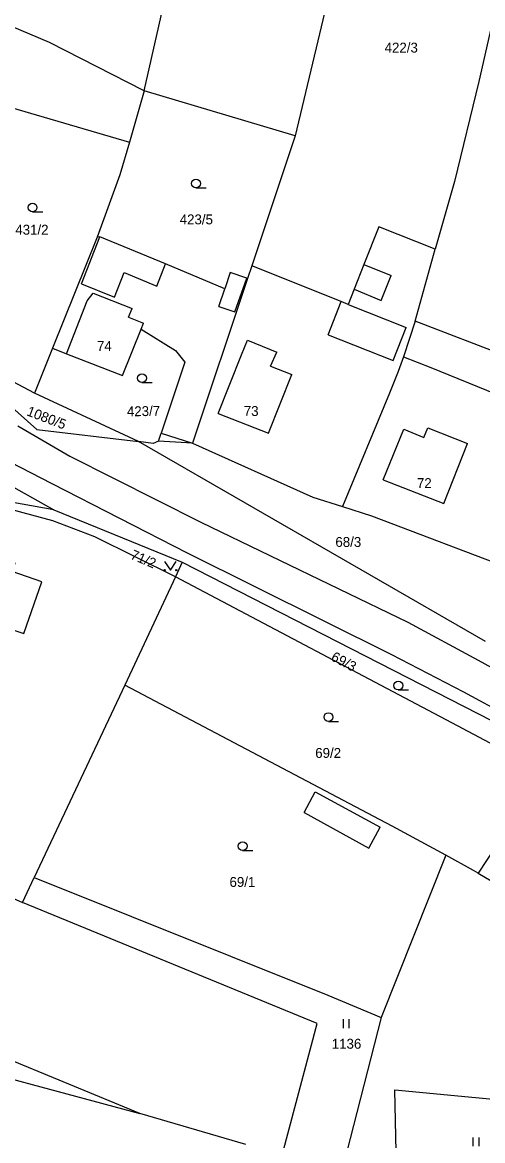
# Model space of a CAD drawing. Extents: x -746176 to -739709, y -1128407 to -1124482.
# Drawn here: x -742472.1 to -742393.3, y -1126052.3 to -1125860.6 of the extents above; entities that cross this region are included whole.
import ezdxf

# ---------------------------------------------------------------- set-up
doc = ezdxf.new("R2010")
doc.units = 0
for name, color, linetype in [('Hranice parcel', 7, 'Continuous'), ('Parcelní čísla', 7, 'Continuous'), ('Vnitřní kresba', 7, 'Continuous'), ('Značky kultur', 7, 'Continuous')]:
    doc.layers.add(name, color=color, linetype=linetype)

msp = doc.modelspace()

# ---------------------------------------------------------------- linework, layer by layer
at = {"layer": 'Hranice parcel'}
for p, q in [((-742411.59, -1125821.74), (-742425.41, -1125880.06)), ((-742491.48, -1125870.12), (-742453.8, -1125881.12)), ((-742451.26, -1125872.3), (-742453.8, -1125881.12)), ((-742425.41, -1125880.06), (-742451.26, -1125872.3)), ((-742425.41, -1125880.06), (-742432.86, -1125902.34)), ((-742459.32, -1125897.41), (-742466.99, -1125916.45)), ((-742404.91, -1125911.78), (-742401.44, -1125899.49)), ((-742432.86, -1125902.34), (-742433.58, -1125904.47)), ((-742433.58, -1125904.47), (-742443.02, -1125932.7)), ((-742470.08, -1125924.13), (-742486.25, -1125915.58)), ((-742466.99, -1125916.45), (-742470.08, -1125924.13)), ((-742452.23, -1125932.44), (-742470.08, -1125924.13)), ((-742392.86, -1125966.72), (-742452.23, -1125932.44)), ((-742485.76, -1125933.54), (-742466.73, -1125944.13)), ((-742466.73, -1125944.13), (-742444.75, -1125953.11)), ((-742444.75, -1125953.11), (-742445.94, -1125955.65)), ((-742445.94, -1125955.65), (-742454.6, -1125974.2)), ((-742454.6, -1125974.2), (-742470.09, -1126007.17)), ((-742399.65, -1126003.37), (-742410.68, -1126031.18)), ((-742472.11, -1126011.47), (-742470.09, -1126007.17)), ((-742452.02, -1126047.65), (-742529.61, -1126015.62)), ((-742410.68, -1126031.18), (-742417.35, -1126057.17)), ((-742433.87, -1126052.94), (-742452.02, -1126047.65))]:
    msp.add_line(p, q, dxfattribs=at)
for points in [[(-742451.26, -1125872.3), (-742423.93, -1125751.58), (-742396.6, -1125630.87)], [(-742451.26, -1125872.3), (-742467.46, -1125864.05), (-742487.36, -1125855.55)], [(-742391.8, -1125861.15), (-742394.01, -1125870.7), (-742398.15, -1125887.84), (-742401.44, -1125899.49)], [(-742453.8, -1125881.12), (-742455.42, -1125886.74), (-742459.32, -1125897.41)], [(-742401.44, -1125899.49), (-742411.12, -1125895.65), (-742413.66, -1125902.11), (-742415.31, -1125906.31), (-742416.34, -1125908.93), (-742417.54, -1125908.45), (-742432.86, -1125902.34)], [(-742433.58, -1125904.47), (-742433.71, -1125904.43), (-742436.54, -1125903.47), (-742437.49, -1125906.29), (-742447.62, -1125901.95), (-742458.86, -1125897.36), (-742459.32, -1125897.41)], [(-742466.99, -1125916.45), (-742464.6, -1125917.38), (-742455, -1125921.11), (-742451.78, -1125913.15), (-742445.93, -1125916.84), (-742444.31, -1125918.83), (-742448.37, -1125931), (-742443.02, -1125932.7)], [(-742404.91, -1125911.78), (-742406.86, -1125917.94), (-742407.78, -1125920.45), (-742409.26, -1125924.16), (-742417.31, -1125943.6)], [(-742376.04, -1125923.32), (-742388.87, -1125917.99), (-742404.91, -1125911.78)], [(-742486.25, -1125915.58), (-742469.64, -1125930.37), (-742452.23, -1125932.44)], [(-742443.02, -1125932.7), (-742448.82, -1125932.36), (-742449.74, -1125932.78), (-742452.23, -1125932.44)], [(-742443.02, -1125932.7), (-742422.4, -1125941.96), (-742417.31, -1125943.6)], [(-742466.73, -1125944.13), (-742476.04, -1125942.52), (-742485.91, -1125941.93), (-742509.68, -1125946.54)], [(-742445.94, -1125955.65), (-742459.75, -1125948.8), (-742466.89, -1125946.02), (-742474.13, -1125944.08), (-742476.37, -1125943.84), (-742485.83, -1125943.85), (-742509.68, -1125946.54)], [(-742417.31, -1125943.6), (-742412.38, -1125945.19), (-742387.99, -1125954.45)], [(-742480.68, -1125962.42), (-742481.12, -1125963.73), (-742480.27, -1125964.02), (-742480.78, -1125965.52), (-742479, -1125966.12), (-742478.49, -1125964.62), (-742477.64, -1125964.9), (-742477.2, -1125963.59), (-742471.89, -1125965.38), (-742468.82, -1125956.52), (-742473.86, -1125954.74), (-742473.34, -1125953.24), (-742475.63, -1125952.43), (-742475.36, -1125951.69), (-742476.67, -1125951.22), (-742476.32, -1125950.24), (-742478.09, -1125949.62), (-742478.44, -1125950.6), (-742479.71, -1125950.15), (-742479.97, -1125950.9), (-742482.31, -1125950.08), (-742485.99, -1125960.63), (-742480.68, -1125962.42)], [(-742444.75, -1125953.11), (-742386.93, -1125982.77), (-742380.97, -1125986.53)], [(-742382.69, -1125989.14), (-742398.6, -1125980.67), (-742445.94, -1125955.65)], [(-742399.65, -1126003.37), (-742408.8, -1125998.36), (-742454.6, -1125974.2)], [(-742525.42, -1125987.39), (-742524.92, -1125987.63), (-742472.11, -1126011.47)], [(-742382.69, -1125989.14), (-742385.4, -1125993.25), (-742394.08, -1126006.45)], [(-742394.08, -1126006.45), (-742394.87, -1126005.98), (-742399.65, -1126003.37)], [(-742470.09, -1126007.17), (-742419.86, -1126027.33), (-742410.68, -1126031.18)], [(-742394.08, -1126006.45), (-742377.42, -1126016.26), (-742373.55, -1126018.6), (-742347.83, -1126023.87), (-742347.76, -1126023.57)], [(-742427.68, -1126054.77), (-742421.67, -1126032.23), (-742472.11, -1126011.47)], [(-742530.79, -1126023.12), (-742529.6, -1126023.26), (-742518.21, -1126026.98), (-742517.74, -1126027.24), (-742518.78, -1126030.97), (-742491.05, -1126037.15), (-742452.02, -1126047.65)], [(-742408.01, -1126059.51), (-742408.36, -1126043.59), (-742380.73, -1126046.24)]]:
    msp.add_lwpolyline(points, dxfattribs=at)
at = {"layer": 'Vnitřní kresba'}
for p, q in [((-742462.03, -1125905.4), (-742458.86, -1125897.36)), ((-742456.37, -1125907.69), (-742454.71, -1125903.47)), ((-742454.71, -1125903.47), (-742449.09, -1125905.82)), ((-742449.09, -1125905.82), (-742447.62, -1125901.95)), ((-742413.66, -1125902.11), (-742408.97, -1125903.96)), ((-742462.03, -1125905.4), (-742456.37, -1125907.69)), ((-742435.76, -1125910.23), (-742433.71, -1125904.43)), ((-742410.72, -1125908.26), (-742408.97, -1125903.96)), ((-742461.01, -1125908.34), (-742459.99, -1125907.02)), ((-742459.99, -1125907.02), (-742453.33, -1125909.63)), ((-742438.5, -1125909.28), (-742437.49, -1125906.29)), ((-742415.31, -1125906.31), (-742410.72, -1125908.26)), ((-742464.6, -1125917.38), (-742461.01, -1125908.34)), ((-742438.5, -1125909.28), (-742435.76, -1125910.23)), ((-742419.77, -1125914.17), (-742417.54, -1125908.45)), ((-742416.34, -1125908.93), (-742406.43, -1125912.88)), ((-742453.97, -1125911.14), (-742453.33, -1125909.63)), ((-742453.97, -1125911.14), (-742451.37, -1125912.13)), ((-742451.78, -1125913.15), (-742451.37, -1125912.13)), ((-742408.63, -1125918.53), (-742406.43, -1125912.88)), ((-742434.59, -1125917.55), (-742433.61, -1125915.09)), ((-742433.61, -1125915.09), (-742428.57, -1125917.11)), ((-742419.77, -1125914.17), (-742408.63, -1125918.53)), ((-742429.64, -1125919.52), (-742428.57, -1125917.11)), ((-742438.62, -1125927.64), (-742434.59, -1125917.55)), ((-742406.86, -1125917.94), (-742402.22, -1125919.77)), ((-742430.01, -1125931), (-742426.02, -1125920.95)), ((-742429.64, -1125919.52), (-742426.02, -1125920.95)), ((-742402.22, -1125919.77), (-742391.15, -1125924.26)), ((-742438.62, -1125927.64), (-742430.01, -1125931)), ((-742472.93, -1125929.77), (-742464.02, -1125934.96)), ((-742410.34, -1125939), (-742406.83, -1125930.35)), ((-742406.83, -1125930.35), (-742403.4, -1125931.74)), ((-742403.4, -1125931.74), (-742402.73, -1125930.07)), ((-742402.73, -1125930.07), (-742395.9, -1125932.8)), ((-742448.82, -1125932.36), (-742448.37, -1125931)), ((-742399.99, -1125943.09), (-742395.9, -1125932.8)), ((-742476.09, -1125935.01), (-742467.07, -1125939.61)), ((-742464.02, -1125934.96), (-742441.6, -1125946.26)), ((-742467.07, -1125939.61), (-742443.89, -1125951.53)), ((-742410.34, -1125939), (-742399.99, -1125943.09)), ((-742441.6, -1125946.26), (-742406.15, -1125963.41)), ((-742443.89, -1125951.53), (-742408.92, -1125968.97)), ((-742406.15, -1125963.41), (-742394.08, -1125969.92)), ((-742408.92, -1125968.97), (-742396.61, -1125975.35)), ((-742394.08, -1125969.92), (-742378.39, -1125978.73)), ((-742396.61, -1125975.35), (-742381.3, -1125983.74)), ((-742423.91, -1125996.04), (-742421.99, -1125992.51)), ((-742421.99, -1125992.51), (-742410.9, -1125998.54)), ((-742423.91, -1125996.04), (-742412.8, -1126002.17)), ((-742412.8, -1126002.17), (-742410.9, -1125998.54))]:
    msp.add_line(p, q, dxfattribs=at)
at = {"layer": 'Značky kultur'}
for p, q in [((-742442.41, -1125888.96), (-742440.66, -1125888.96)), ((-742470.38, -1125893.06), (-742468.63, -1125893.06)), ((-742451.65, -1125922.32), (-742449.9, -1125922.32)), ((-742407.77, -1125975.03), (-742406.02, -1125975.03)), ((-742419.74, -1125980.43), (-742417.99, -1125980.43)), ((-742434.42, -1126002.55), (-742432.67, -1126002.55)), ((-742417.16, -1126032.99), (-742417.16, -1126031.49)), ((-742416.16, -1126032.99), (-742416.16, -1126031.49)), ((-742394.93, -1126053.24), (-742394.93, -1126051.74)), ((-742393.93, -1126053.24), (-742393.93, -1126051.74))]:
    msp.add_line(p, q, dxfattribs=at)
msp.add_lwpolyline([(-742447.78, -1125952.99), (-742446.78, -1125954.49), (-742445.78, -1125952.99)], dxfattribs=at)
for centre, radius in [((-742442.41, -1125888.21), 0.75), ((-742470.38, -1125892.31), 0.75), ((-742451.65, -1125921.57), 0.75), ((-742447.78, -1125954.49), 0.1), ((-742445.78, -1125954.49), 0.1), ((-742407.77, -1125974.28), 0.75), ((-742419.74, -1125979.68), 0.75), ((-742434.42, -1126001.8), 0.75)]:
    msp.add_circle(centre, radius, dxfattribs=at)

# ---------------------------------------------------------------- texts
at = {"layer": 'Parcelní čísla'}
for s, p in [('422/3', (-742410.11, -1125865.76)), ('423/5', (-742445.19, -1125895.21)), ('431/2', (-742473.34, -1125896.98)), ('74', (-742459.36, -1125916.92)), ('73', (-742434.22, -1125928.06)), ('72', (-742404.58, -1125940.42)), ('68/3', (-742418.54, -1125950.51)), ('69/2', (-742421.99, -1125986.68)), ('69/1', (-742436.67, -1126008.8)), ('1136', (-742419.16, -1126036.54))]:
    msp.add_text(s, height=1.7, dxfattribs=at).set_placement(p)
for s, rotation, p in [('1080/5', 339, (-742471.53, -1125927.91)), ('423/7', 1, (-742454.22, -1125928.13)), ('71/2', 337, (-742453.77, -1125952.49)), ('69/3', 332, (-742419.43, -1125969.87))]:
    msp.add_text(s, height=1.7, rotation=rotation, dxfattribs=at).set_placement(p)

doc.saveas('drawing.dxf')
